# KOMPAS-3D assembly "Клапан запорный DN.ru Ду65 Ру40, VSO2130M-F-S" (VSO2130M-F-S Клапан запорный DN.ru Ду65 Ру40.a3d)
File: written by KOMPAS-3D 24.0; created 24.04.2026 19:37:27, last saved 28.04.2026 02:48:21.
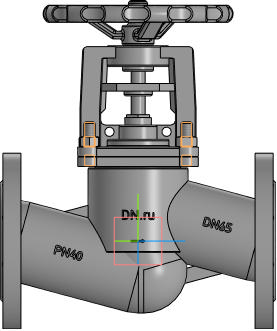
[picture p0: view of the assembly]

Document properties: Автор: DN.ru; Полное имя файла: C:\Работа\ГОТОВЫЕ ИСХОДНИКИ\VSO2130M-F-S Клапан запорный сильфонный DN.ru Ду15-100 Ру40\исходные материалы\DN65\VSO2130M-F-S Клапан запорный DN.ru Ду65 Ру40.a3d

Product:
- Component [detail]: Корпус  | qty 1  | pos. 1  | Масса: 6.9; Автор: R2D2; source file: Korpus.m3d
- Component [detail]: Деталь  | qty 1  | pos. 2  | Автор: mrdid; source file: rama.m3d
- Component [detail]: Деталь2  | qty 1  | pos. 3  | Автор: R2D2; additional columns: Типовые; source file: shturval.m3d
- Component [standard]: Шпилька М12-6gx35 ГОСТ 22032-76  | qty 4  | Масса: 0.03564; Раздел спецификации: Стандартные изделия; Рассекать на разрезах: no
- Component [standard]: Гайка М12-6H ГОСТ 5915-70  | qty 4  | Масса: 0.0184; Раздел спецификации: Стандартные изделия; Рассекать на разрезах: no
- Body: Тело 1  | qty 1
    Масса: 5.843392
- Part/product: Клапан запорный DN.ru Ду65 Ру40  | designation VSO2130M-F-S
    Масса: 17
    Раздел спецификации: Прочие изделия
    Примечание: D090-01976

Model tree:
1. Контекстная связь:1  (with: Эскиз:2, Ребро.Элемент выдавливания:14, Контекстная связь (Деталь):1)
2. Контекстная связь:2  (with: Контекстная связь (Деталь):2)
3. Массив по концентрической сетке:1  (4 pattern instances)
     Шаг 2 = 360
4. Эскиз:1  (with: Грань.Элемент выдавливания:9)
5. Элемент выдавливания:1  (with: Грань.Элемент выдавливания:1, Грань.Элемент выдавливания:15, Грань.Элемент выдавливания:3, Грань.Элемент выдавливания:2, Грань.Элемент выдавливания:16, Грань.Элемент выдавливания:17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)  (labels: Грань.Твердое тело1)
     Расстояние 1 = 10; Угол = 8

Referenced files in C:\Работа\ГОТОВЫЕ ИСХОДНИКИ\VSO2130M-F-S Клапан запорный сильфонный DN.ru Ду15-100 Ру40\исходные материалы\DN65\: Korpus.m3d, rama.m3d, shturval.m3d
Referenced files in C:\Program Files\ASCON\KOMPAS-3D v24\Libs\PolynomLib\DATA\vault\Methods\Kompas\3D\: PLib_Stud_1_900.m3d, PLib_Nut_OST92_900.m3d
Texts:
  Программные изделия  и базы данных
  Крепежное изделие ГОСТ
  BOSimple***PART:6f4e1f7b-338b-881e-0b64-6bd1e4faf7a4***SHORTLOC:Root±30±20±10±120±10±20[Нет;Без покрытия;Без указания материала;-;12;35;1,75;1,75]
  BOSimple***PART:dfaf85ed-3e43-003f-b29c-9c5b054070d3***SHORTLOC:Root±30±10±20±©{}110±10±50±60[Нет;Без покрытия;Без указания материала;-;12;1,75;19]
  VSO2130M-F-S
  Деталь2 Деталь2
  Шпилька М12-6gx35 ГОСТ 22032-76 (1)
  cut1
  Гайка М12-6H ГОСТ 5915-70 (1)
  bcut1
  hole1
  hcut1
  hole2
  Плоскость XY.Начало координат
  Plane. Начало координат
  Твердое тело1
